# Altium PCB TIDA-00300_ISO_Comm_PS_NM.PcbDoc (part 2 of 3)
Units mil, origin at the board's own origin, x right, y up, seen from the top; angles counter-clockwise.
Board outline 2559.06 x 6299.21 mil, 4 copper layers (Top Layer, GND Layer, PWR Layer, Bottom Layer), stack 61.6 mil thick; 303 components, 144 nets, 678 pads, 244 vias.
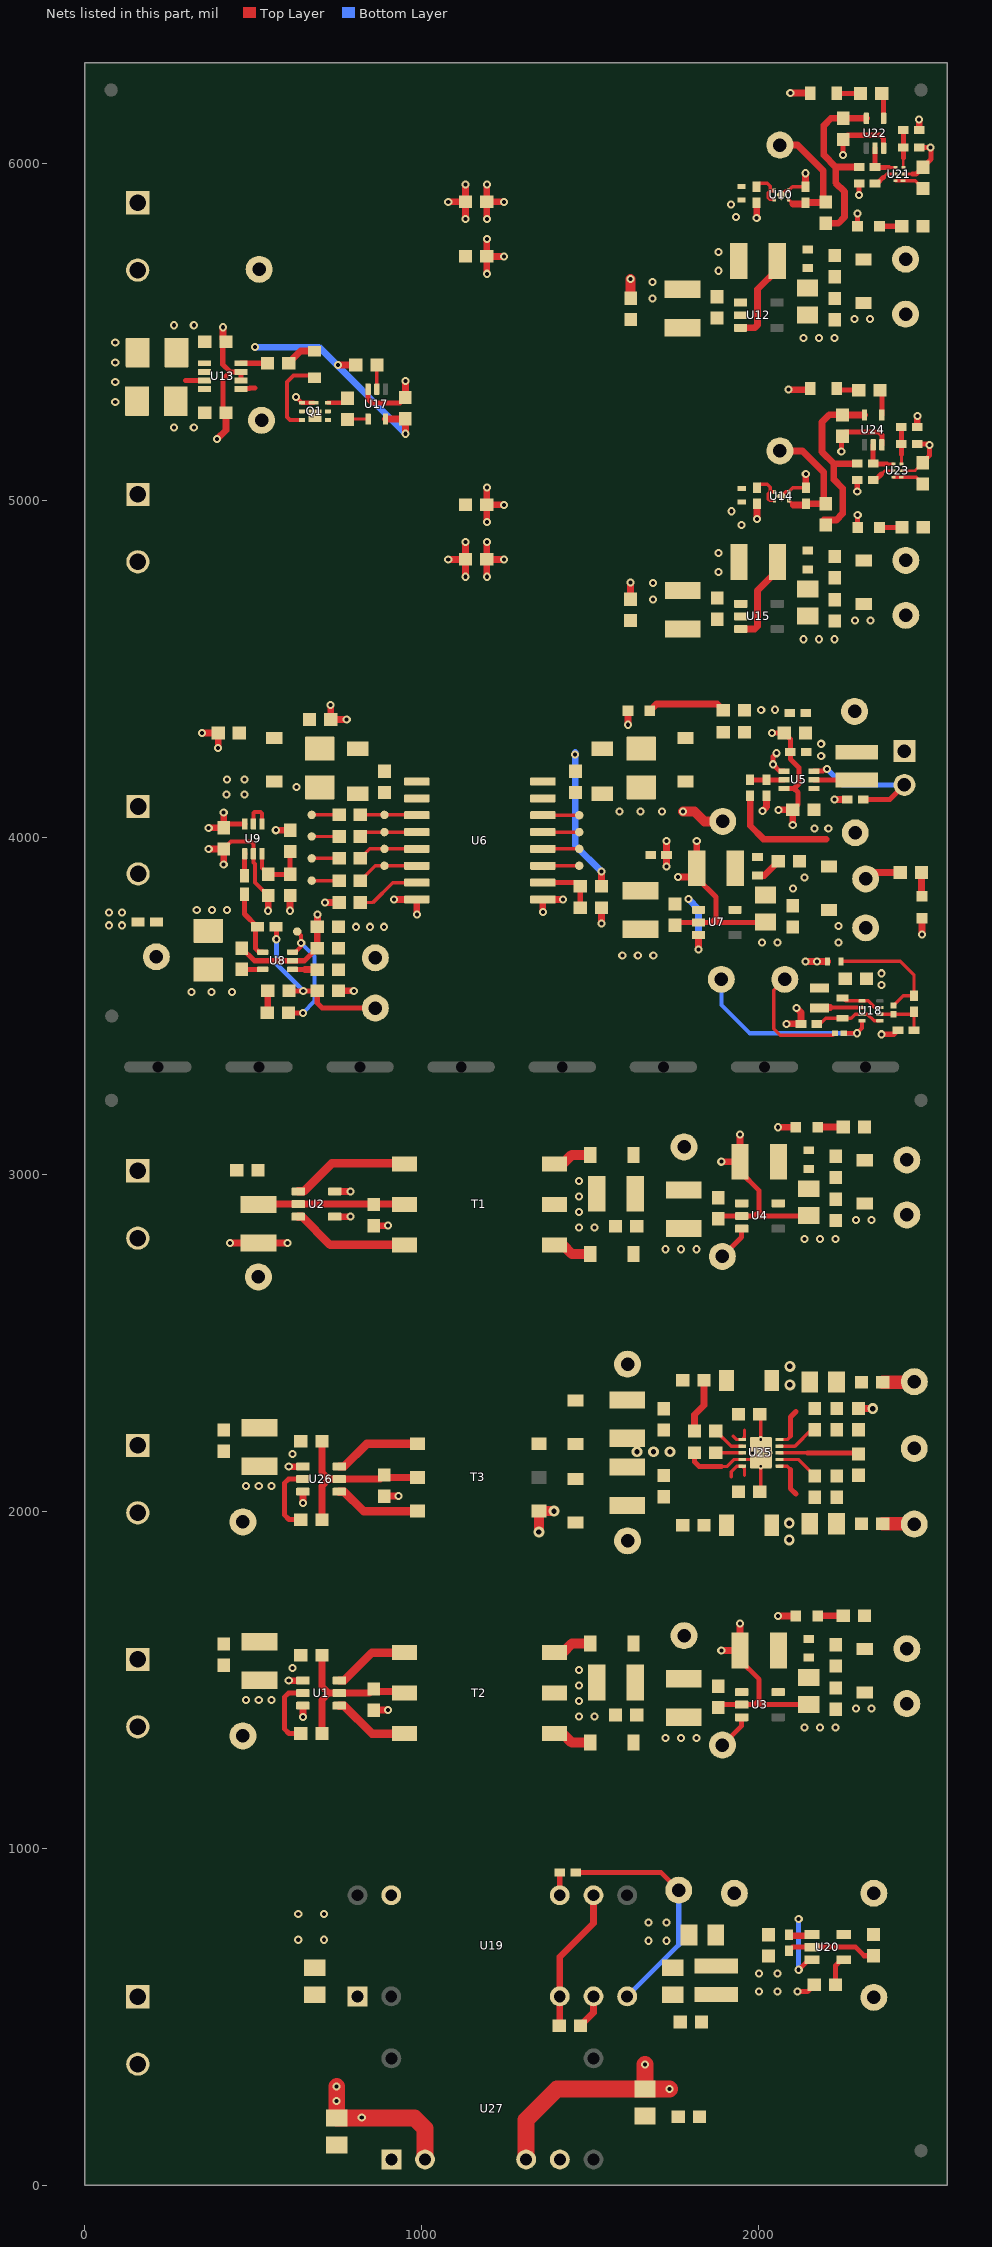
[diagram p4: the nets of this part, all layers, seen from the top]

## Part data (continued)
L8: library part CMP-0058850-1, "Inductor, Wirewound, Ferrite, 15 uH, 0.37 A, 0.91 ohm, SMD", Manufacturer=MuRata, Supplier Part Number 1=490-5124-1-ND, Value1="0.91 ohm", Value2=0.37A, ValueDisplayed=15uH
Logo2: library part Pb-Free
Logo3: library part FCC_disclaimer, "FCC_disclaimer"
Logo4: library part CMP-0074769-1
Logo5: library part ESD_Susceptible, "ESD Susceptible Symbol"
Q1: "MOSFET, N-CH, 30 V, 22 A, DQK0006C (WSON-6)", Alternate Manufacturer=None, Manufacturer="Texas Instruments", Supplier Part Number 1=296-37193-1-ND, Value1="0.029 ohm", Value2="2.4 nC"
R1 R2 R3 R4 R5 R23 R40 R47 R82 R85 R94 R95: "RES, 0 ohm, 5%, 0.1W, 0603", Manufacturer=Vishay-Dale, Power_W=0.1, Supplier Part Number 1=541-0.0GCT-ND, TempCo="200 ppm/C", Tolerance_%=5, Value1=5%, Value2=0.1W, Value_Code=0000
R6 R7 R11: "RES, 820, 1%, 0.1 W, 0603", Manufacturer="Yageo America", Power_W=0.1, Supplier Part Number 1=311-820HRCT-ND, TempCo="200 ppm/C", Tolerance_%=1, Value1=1%, Value2=0.1W, Value_Code=820R, ValueDisplayed=820
R8 R9 R10 R20 R22 R25 R35 R36 R37 R38 R61 R63 R72 R77 R83 R84 R89 R90 R92: "RES, 0, 5%, 0.1 W, 0603", Manufacturer=Vishay-Dale, Power_W=0.1, Supplier Part Number 1=541-0.0GCT-ND, TempCo="200 ppm/C", Tolerance_%=5, Value1=5%, Value2=0.1W, Value_Code=0000, ValueDisplayed=0
R12 R65 R70: "RES, 0, 5%, 0.063 W, 0402", Manufacturer=Vishay-Dale, Power_W=0.063, Supplier Part Number 1=541-0.0JCT-ND, TempCo="200 ppm/C", Tolerance_%=5, Value1=5%, Value2=0.063W, Value_Code=0000, ValueDisplayed=0
R13 R15: "RES, 1.00 M, 1%, 0.063 W, 0402", Manufacturer=Vishay-Dale, Power_W=0.063, Supplier Part Number 1=541-1.00MLCT-ND, TempCo="100 ppm/C", Tolerance_%=1, Value1=1%, Value2=0.063W, Value_Code=1M00, ValueDisplayed=1.00M
R14 R16 R18 R19: "RES, 49.9, 1%, 0.1 W, 0603", Manufacturer=Vishay-Dale, Power_W=0.1, Supplier Part Number 1=541-49.9HCT-ND, TempCo="100 ppm/C", Tolerance_%=1, Value1=1%, Value2=0.1W, Value_Code=49R9, ValueDisplayed=49.9
R17 R60: "RES, 100 k, 1%, 0.0625 W, 0402", Manufacturer="Yageo America", Power_W=0.0625, Supplier Part Number 1=311-100KLRCT-ND, TempCo="100 ppm/C", Tolerance_%=1, Value1=1%, Value2=0.0625W, Value_Code=100k
R21: "RES, 4.7 k, 5%, 0.1 W, 0603", Manufacturer="Yageo America", Power_W=0.1, Supplier Part Number 1=311-4.7KGRCT-ND, TempCo="100 ppm/C", Tolerance_%=5, Value1=5%, Value2=0.1W, Value_Code=4k70, ValueDisplayed=4.7k
R24 R41 R48 R54 R75 R80: "RES, 680, 1%, 0.1 W, 0603", Manufacturer="Yageo America", Power_W=0.1, Supplier Part Number 1=311-680HRCT-ND, TempCo="200 ppm/C", Tolerance_%=1, Value1=1%, Value2=0.1W, Value_Code=680R, ValueDisplayed=680
R26 R29 R71: "RES, 47 k, 5%, 0.1 W, 0603", Manufacturer="Yageo America", Power_W=0.1, Supplier Part Number 1=311-47KGRCT-ND, TempCo="100 ppm/C", Tolerance_%=5, Value1=5%, Value2=0.1W, Value_Code=47k0, ValueDisplayed=47k
R27: "RES, 2.20 k, 1%, 0.1 W, 0603", Manufacturer="Yageo America", Power_W=0.1, Supplier Part Number 1=311-2.20KHRCT-ND, TempCo="200 ppm/C", Tolerance_%=1, Value1=1%, Value2=0.1W, Value_Code=2k20, ValueDisplayed=2.20k
R28 R31 R32: "RES, 0 ohm, 5%, 0.063W, 0402", Manufacturer="Yageo America", Power_W=0.063, Supplier Part Number 1=311-0.0JRCT-ND, TempCo="200 ppm/C", Tolerance_%=5, Value1=5%, Value2=0.063W, Value_Code=0000
R30 R33: "RES, 162 k, 1%, 0.1 W, 0603", Manufacturer="Yageo America", Power_W=0.1, Supplier Part Number 1=311-162KHRCT-ND, TempCo="200 ppm/C", Tolerance_%=1, Value1=1%, Value2=0.1W, Value_Code=162k
R34 R44 R57: library part CMP-0027004-2, "RES, 0, 5%, 0.063 W, 0402", Manufacturer="Yageo America", Power_W=63mW, Supplier Part Number 1=311-0.0JRCT-ND, TempCo="200 ppm/C", Tolerance_%=5%, Value2=0.063W, Value_Code=0000, ValueDisplayed=0
R55: "RES, 300, 5%, 0.1 W, 0603", Manufacturer=Vishay-Dale, Power_W=0.1, Supplier Part Number 1=541-300GCT-ND, TempCo="200 ppm/C", Tolerance_%=5, Value1=5%, Value2=0.1W, Value_Code=300R, ValueDisplayed=300
R56: "RES, 0, 1%, 0.1 W, AEC-Q200 Grade 0, 0603", Manufacturer="Stackpole Electronics Inc", Power_W=0.1, Supplier Part Number 1=RMCF0603ZT0R00CT-ND, TempCo=ppm/C, Tolerance_%=1, Value1=1%, Value2=0.1W, Value_Code=0
R58: "RES, 453 k, 1%, 0.063 W, 0402", Manufacturer=Vishay-Dale, Power_W=0.063, Supplier Part Number 1=541-453KLCT-ND, TempCo="100 ppm/C", Tolerance_%=1, Value1=1%, Value2=0.063W, Value_Code=453k
R59: library part CMP-0027293-2, "RES, 100 k, 1%, 0.05 W, 0201", Manufacturer="Yageo America", Power_W=50mW, Supplier Part Number 1=311-100KMCT-ND, TempCo="200 ppm/C", Tolerance_%=1%, Value2=0.05W, Value_Code=100k
R73 R78: "RES, 68 k, 5%, 0.063 W, 0402", Manufacturer=Vishay-Dale, Power_W=0.063, Supplier Part Number 1=541-68KJCT-ND, TempCo="200 ppm/C", Tolerance_%=5, Value1=5%, Value2=0.063W, Value_Code=68k0, ValueDisplayed=68k
R74 R76 R79 R81 R93: "RES, 10.0 k, 1%, 0.063 W, 0402", Manufacturer=Vishay-Dale, Power_W=0.063, Supplier Part Number 1=541-10.0KLCT-ND, TempCo="100 ppm/C", Tolerance_%=1, Value1=1%, Value2=0.063W, Value_Code=10k0, ValueDisplayed=10.0k
R86 R87: "RES, 274 k, 1%, 0.1 W, 0603", Manufacturer=Vishay-Dale, Power_W=0.1, Supplier Part Number 1=541-274KHCT-ND, TempCo="100 ppm/C", Tolerance_%=1, Value1=1%, Value2=0.1W, Value_Code=274k
R88: "RES, 31.6 k, 1%, 0.1 W, 0603", Manufacturer=Vishay-Dale, Power_W=0.1, Supplier Part Number 1=541-31.6KHCT-ND, TempCo="100 ppm/C", Tolerance_%=1, Value1=1%, Value2=0.1W, Value_Code=31k6, ValueDisplayed=31.6k
R91: "RES, 27.4 k, 1%, 0.1 W, 0603", Manufacturer=Vishay-Dale, Power_W=0.1, Supplier Part Number 1=541-27.4KHCT-ND, TempCo="100 ppm/C", Tolerance_%=1, Value1=1%, Value2=0.1W, Value_Code=27k4, ValueDisplayed=27.4k
T1 T2: library part 750313734, "Transformer, 340 uH, TH", Manufacturer="Wurth Elektronik", Supplier Part Number 1=1297-1105-1-ND, ValueDisplayed=340µH
T3: library part CMP-0030718-1, "Transformer, 475uH, SMT", Manufacturer="Wurth Elektronik", Supplier Part Number 1=732-4458-1-ND, ValueDisplayed=475uH
TP1 TP2 TP7 TP8 TP11 TP12 TP19 TP27 TP28 TP29 TP30 TP33 TP36 TP38 TP39 TP41 TP51 TP53 TP54 TP55 TP56 TP59 TP60 TP61: "Test Point, Miniature, Red, TH", Color=Red, Manufacturer=Keystone, Supplier Part Number 1=36-5000-ND
TP3 TP4 TP5 TP6 TP23 TP26 TP35 TP43 TP52 TP57 TP58: "Test Point, Miniature, Black, TH", Color=Black, Manufacturer=Keystone, Supplier Part Number 1=36-5001-ND
TP9 TP10 TP31: "Test Point, Miniature, White, TH", Color=White, Manufacturer=Keystone, Supplier Part Number 1=36-5002-ND
TP13 TP14 TP15 TP16 TP17 TP18 TP20 TP21 TP22 TP45 TP46 TP47 TP48: "Test Point, O.025\"", Manufacturer=STD
U1 U26: "LOW-NOISE 1A TRANSFORMER DRIVERS FOR ISOLATED POWER SUPPLIES, DBV0006A", Alternate Manufacturer="Texas Instruments", Alternate PartNumber=SN6505BDBVT
U2: "Transformer Driver for Isolated Power Supplies, DBV0005A", Alternate Manufacturer="Texas Instruments", Alternate PartNumber=SN6501DBVT, Supplier Part Number 1=296-37700-1-ND
U3: library part CMP-0073793-1, "150-mA, 30-V, Ultra-Low IQ, Wide Input Low-Dropout Regulator with Reverse Current Protection, DBV0005A (SOT-23-5)", Alternate Manufacturer="Texas Instruments", Alternate PartNumber=TPS70933DBVT
U4: library part CMP-0066783-1, "150-mA, 30-V, Ultra-Low IQ, Wide Input Low-Dropout Regulator with Reverse Current Protection, DBV0005A (SOT-23-5)", Alternate Manufacturer="Texas Instruments", Alternate PartNumber=TPS70950DBVT
U5: library part CMP-0067204-1, "Low Input Voltage, 0.7V Boost Converter with 5.5uA Quiescent Current, DCK0006A (SOT-SC70-6)", Alternate Manufacturer="Texas Instruments", Alternate PartNumber=TPS61220DCKT
U6: library part ISOW7841DWR, "ISOW7841DWE, DW0016B (SOIC-16)", Alternate Manufacturer="Texas Instruments", Alternate PartNumber=ISOW7841DW, Supplier Partnumber 1=296-45475-1-ND
U7: library part CMP-0035560-1, "Single Output LDO, 150 mA, Fixed 5 V Output, 2.7 to 10 V Input, with Low IQ, 5-pin SOT-23 (DBV), -40 to 125 degC, Green (RoHS & no Sb/Br)", Manufacturer="Texas Instruments"
U8: "LOW-INPUT-VOLTAGE CURRENT-LIMITED LOAD SWITCHES WITH SHUT OFF AND AUTO-RESTART FEATURE, DCK0005A (SOT-5)", Alternate Manufacturer="Texas Instruments", Supplier Part Number 1=296-25218-1-ND
U9: "Nanopower, 1.8V, Comparator with Voltage Reference, DCK0006A", Alternate Manufacturer="Texas Instruments", Alternate PartNumber=TLV3012AIDCKT, Supplier Part Number 1=296-26816-1-ND
U10 U14: library part CMP-0079101-1, "200-mA, Small Size, Low-Dropout Linear Voltage Regulator, DQN0004A (X2SON-4)", Alternate Manufacturer="Texas Instruments"
U12 U15: "Single Output LDO, 150 mA, Fixed 5 V Output, 2.5 to 24 V Input, with Ultra-Low IQ, 5-pin SOT-23 (DBV), -40 to 125 degC, Green (RoHS & no Sb/Br)", Alternate Manufacturer="Texas Instruments", Alternate PartNumber=Equivalent, Supplier Part Number 1=296-39287-1-ND
U13: library part CMP-0066654-1, "5.5V, 0.5A, 435mO, 2-Channel Load Switch with Quick Output Discharge, DCN0008A (SOT-23-8)", Alternate Manufacturer="Texas Instruments"
U17: library part CMP-0051641-4, "Single Schmitt-Trigger Inverter, DCK0005A (SOT-SC70-5)", Alternate Manufacturer="Texas Instruments", Alternate PartNumber=SN74LVC1G14DCKT, F @ Nom Voltage(Max)(Mhz)=150, Generic Part Number=SN74LVC1G14, ICC @ Nom Voltage(Max)(mA)=0.01, Operating Temperature Range="-40 to 125 C", Rating=Catalog, tpd @ Nom Voltage(Max)(ns)=11,6.5,5.5,5, Voltage(Nom)(V)=1.8,2.5,3.3,5
U18: library part CMP-0065148-3, "1A Step-Down Converter With 1% Accuracy, DLC0008A (VSON-HR-8)", Alternate Manufacturer="Texas Instruments"
U19: library part CMP-0030829-1, "Miniature, 1 W Isolated Regulated DC-DC Converter, -40 to 85 degC, 10-pin DIP (NVE10), Pb-Free (RoHS)", Manufacturer="Texas Instruments"
U20: "Micropower 150 mA Low-Noise Ultra Low-Dropout Regulator, 5-pin SOT-23, Pb-Free", Manufacturer="Texas Instruments", PackageTopMarking=L0RA*XTT, PowerWise=N, Supplier Part Number 1=LP2985AIM5-3.3CT-ND
U21: library part CMP-0032427-1, "Single Channel, Ultra Small, Adjustable Supervisory Circuit with Active-High, Open-Drain Output, 1 Supply Monitored, -40 to 125 degC, 6-pin SON (DRY), Green (RoHS & no Sb/Br)", Manufacturer="Texas Instruments", Rating=Catalog, Threshold Voltage 1 (typ)(Typ)(V)=Adjustable
U22 U24: library part CMP-0051704-1, "Single Schmitt-Trigger Buffer, DCK0005A, LARGE T&R", F @ Nom Voltage(Max)(Mhz)=150, Generic Part Number=SN74LVC1G17, ICC @ Nom Voltage(Max)(mA)=0.01, Manufacturer="Texas Instruments", Operating Temperature Range(C)="-40 to 125,-40 to 85", Rating=Catalog, tpd @ Nom Voltage(Max)(ns)=11,6.5,5.5,5, Voltage(Nom)(V)=1.8,2.5,3.3,5
U23: library part CMP-0032419-1, "Single Channel, Ultra Small, Adjustable Supervisory Circuit with Active-High, Push-Pull Output, 1 Supply Monitored, -40 to 125 degC, 6-pin SON (DRY), Green (RoHS & no Sb/Br)", Manufacturer="Texas Instruments", Rating=Catalog, Threshold Voltage 1 (typ)(Typ)(V)=Adjustable
U25: "Wide-VIN (±33 V), 150-mA, Spilt-Rail Output, Positive and Negative LDO Voltage Regulator with Startup Tracking, DSC0010J", Alternate Manufacturer="Texas Instruments", Supplier Part Number 1=296-47504-1-ND
U27: library part CMP-0030762-1, "Miniature, 1 W Isolated Unregulated DC-DC Converter, -40 to 100 degC, 7-pin DIP (NVA7), Pb-Free (RoHS)", Manufacturer="Texas Instruments"
ZZ1: library part AssemblyNoteLabel
ZZ2 ZZ3 ZZ4: library part AssemblyNote

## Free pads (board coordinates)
  oval 200x32 hole 32 slot 200 at 0 deg unplated mask+10: 0(216.42,3318.94) 0(516.42,3318.94) 0(816.42,3318.94) 0(1116.42,3318.94) 0(1416.42,3318.94) 0(1716.42,3318.94) 0(2016.42,3318.94) 0(2316.42,3318.94)

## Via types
v1: diameter 24, hole 12, Top Layer to Bottom Layer, 230 vias
v2: diameter 32, hole 16, Top Layer to Bottom Layer, 10 vias
v3: diameter 19.68, hole 7.87, Top Layer to Bottom Layer, 4 vias

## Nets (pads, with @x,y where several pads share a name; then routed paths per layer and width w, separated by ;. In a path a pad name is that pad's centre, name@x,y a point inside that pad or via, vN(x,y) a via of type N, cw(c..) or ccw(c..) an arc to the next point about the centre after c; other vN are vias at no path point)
+3.3V_6: C79.1 TP53.1 U20.5
+3.3V_VDC_1: D5.1 R4.2 R7.2 TP7.1
+5.0V_3.3V_VDC_4: C82.1 C83.1 D16.1 R40.2 R41.2 R72.1 R74.1 TP33.1 U21.1 U21.6 U22.5 | length 657.4
  Top Layer w10: U21.6@2405.03,5948.79 U21.1@2427.67,5948.79 2427.67,5948.11 2464.42,5948.11 C82.1@2486.84,5925.69
  Top Layer w20: R72.1@2198,5822.35 2235.5,5822.35 2254,5840.85 2254,5916.13 2227.79,5942.34 2227.79,5989.06 ; R74.1@2297.22,5989.06 2227.79,5989.06 ; U22.5@2318.87,6133.77 2250.05,6133.77 C83.1@2249.84,6133.98 2213.89,6133.98 2192.47,6112.56 2192.47,6024.38 2227.79,5989.06
+5.0V_3.3V_VDC_5: C85.1 C86.1 D20.1 R47.2 R48.2 R77.1 R79.1 TP41.1 U23.1 U23.6 U24.5 | length 661.7
  Top Layer w10: U23.6@2399.56,5068.66 U23.1@2422.19,5068.66 ; U23.1@2422.19,5067.97 U23.1@2422.19,5068.66 ; C85.1@2486.57,5048.53 2466.43,5068.66 U23.1@2422.19,5068.66
  Top Layer w20: R77.1@2192.53,4942.22 2230.03,4942.22 2248.53,4960.72 2248.53,5035.99 2222.31,5062.21 2222.31,5108.93 ; R79.1@2291.75,5108.93 2222.31,5108.93 ; U24.5@2313.4,5253.64 2244.57,5253.64 2244.37,5253.84 2208.42,5253.84 2187,5232.42 2187,5144.24 2222.31,5108.93
+5.0V_VDC_2: D6.1 R5.2 R6.2 TP8.1
+5.0V_VDC_3: C33.2 C34.1 D12.1 R23.2 R24.2 R57.2 TP28.1 | length 176
  Top Layer w20: v1(2138.26,3631.85) v1(2172.77,3631.85) R57.2@2203.82,3631.85 ; TP28.1@2316.77,3876.85 2335.88,3895.96 R24.2@2419.27,3895.96
  other v1: 2100.84,3847.85 2135.14,3881.53
+5V_1: J1.1 R1.2
+5V_2: J2.1 R2.2
+5V_B: J8.1 R82.2
+5V_VDC_6: C75.1 C77.1 C78.1 L8.2 TP51.1 U20.1 U20.3 | length 272.9
  Top Layer w15: v1(2118,640) 2147.6,669.6 U20.3@2157.39,669.6
  Top Layer w20: C78.1@2088.64,743.62 2091.26,741 2153.99,741 U20.1@2157.39,744.4
  Bottom Layer w15: v1(2118,640) v1(2118,790)
+6V_VDC_1: C8.1 C9.1 C10.2 C12.1 D2.1 D4.1 TP2.1 U3.1
+6V_VDC_2: C6.1 C7.1 C11.2 C13.1 D1.1 D3.1 TP1.1 U4.1
+12V: R83.2 TP56.1 | length 94.4
  Top Layer w40: R83.2@2367.07,2383.67 2459.82,2383.67 TP56.1@2461,2384.85
-12V: R92.2 TP60.1 | length 94.3
  Top Layer w40: R92.2@2367.07,1963.67 2459.58,1963.67 TP60.1@2460.86,1962.39
C\S\: R18.2 TP47.1 | length 81.5
  Top Layer w10: TP47.1@672.77,3937.85 R18.2@754.27,3937.85
DVDD_3: C29.1 C30.2 C37.1 R8.2 R20.2 R26.2 R30.2 R32.2 R71.2 TP27.1 U8.5 U9.6 | length 461.1
  Top Layer w15: C37.1@411.77,4028.35 423.56,4040.14 U9.6@474.18,4040.14 ; C30.2@465.57,3608.5 465.66,3608.4 U8.5@527.48,3608.4
  Top Layer w20: v1(347.77,4309.85) R8.2@395.27,4309.85 395.27,4265.35 v1(394.77,4264.84) ; v1(367.27,4028.35) C37.1@411.77,4028.35 ; C37.1@411.77,4028.85 v1(411.77,4073.35) ; R71.2@541.27,3479.14 542.27,3480.14 R26.2@542.27,3544.85 ; v1(566.27,4021.35) R30.2@608.77,4021.35 ; v1(712.77,3806.85) R20.2@754.27,3806.85
  other v1: 315.77,3541.85 375.77,3541.85 435.77,3541.85
DVDD_4: C52.1 C53.2 J5.2 U13.1 U13.2
  other v1: 264,5519.8 323,5519.8
DVDD_5: C54.1 C55.2 J6.1 U13.3 U13.4 | length 55.9
  Top Layer w15: 299,5355.8 U13.3@354.87,5355.8
  other v1: 264,5215.8 323,5215.8
DVDD_I_3: R9.2 R11.2 R12.1 R65.2 TP11.1 | length 95.4
  Top Layer w20: v1(2081.77,3446.85) 2124.28,3446.85 R65.2@2124.67,3446.46 2124.67,3480.53 v1(2111.77,3493.43)
  other v1: 2006.77,4377.85 2047.72,4378.85
DVDD_I_4: R34.1 R35.1 R61.2 R73.2 | length 242.9
  Top Layer w20: v1(1192.5,5672.5) R35.1@1192.5,5724 ; v1(1192.5,5775.5) R35.1@1192.5,5724 ; v1(1243.99,5724) R35.1@1192.5,5724 ; R73.2@2475.46,6098.48 v1(2475.46,6130.39)
  Top Layer w30: R61.2@1619.42,5599.99 v1(1619.42,5656.44)
  other v1: 1932.42,5841.49 1917.42,5878.52
DVDD_I_5: R37.1 R44.1 R63.2 R78.2 | length 236.6
  Top Layer w20: v1(1192.5,4935.5) R37.1@1192.5,4987 ; v1(1192.5,5038.5) R37.1@1192.5,4987 ; v1(1243.99,4987) R37.1@1192.5,4987 ; v1@1618.74,4756.8 v1(1619,4756.55) R63.2@1619,4706.66 ; R78.2@2469.99,5218.35 v1(2469.99,5250.25)
  other v1: 1948.07,4926.8 1919,4967.8
DVDD_I_5.4V_3: C28.1 R13.2 R70.1 TP12.1 U5.4 | length 408
  Top Layer w20: v1(1725.72,3913.32) R70.1@1725.72,3947.85 v1(1725.72,3989.84) ; R13.2@1974.11,4123.99 1974.11,4034.57 2013.84,3994.85 2199.77,3994.85
  other v1: 2164.77,4026.85 2205.77,4026.85
GND_1: C2.1 C3.1 C5.1 J1.2 TP3.1 U1.4 U1.6 | length 117.5
  Top Layer w15: U1.6@646.61,1423.45 U1.6@646.74,1423.31
  Top Layer w20: v1(604.74,1497.85) 646.21,1497.85 U1.4@646.48,1498.12 ; v1(646.74,1389.85) U1.6@646.74,1423.31 ; C5.1@856.88,1410.49 857.24,1410.85 v1(898.74,1410.85)
  other v1: 477.74,1440.85 515.74,1440.85 553.74,1440.85 615.74,1534.85
GND_2: C1.1 C4.1 J2.2 TP4.1 U2.4 U2.5 | length 305.9
  Top Layer w20: v1(430.83,2796.72) C1.1@514.74,2796.72 v1(601.66,2796.72) ; U2.4@741.36,2874.64 v1(787.91,2874.64) ; U2.5@741.36,2949.44 v1(787.91,2949.44) ; C4.1@856.88,2847.58 857.24,2847.94 v1(898.74,2847.94)
GND_3: C20.1 C22.2 C24.2 C29.2 C30.1 C36.1 C37.2 C38.2 D9.2 J4.1 R27.2 R29.1 R33.1 U6.2 U6.8 U8.2 U9.2 | length 965.4
  Top Layer w12: C37.2@411.77,3965.35 433.81,3987.39 493.49,3987.39 499.77,3981.12 U9.2@499.77,3951.56 499.77,3925.59 504.77,3920.59 504.77,3866.35 R33.1@543.77,3827.35
  Top Layer w15: C30.1@465.57,3671.49 503.06,3633.99 U8.2@616.06,3633.99 651.77,3633.99 C36.1@689.27,3671.49
  Top Layer w20: v1(367.27,3965.35) C37.2@411.77,3965.35 v1(411.77,3919.95) ; v1(543.77,3782.35) R33.1@543.77,3827.35 ; v1(608.7,3782.35) C38.2@608.7,3827.35 ; C36.1@689.27,3671.49 R27.2@689.27,3734.85 689.77,3735.35 v1(689.77,3771.85) ; R29.1@752.26,3544.85 v1(797.77,3544.85) ; v1(916.77,3815.85) U6.8@984.76,3815.85 v1(984.76,3770.86)
  other v1: 331.77,3785.17 376.77,3784.85 421.77,3784.54 419.77,4126.85 473.45,4126.85 627.77,4149.17 421.08,4171.85 473.77,4171.85
GND_4: C52.2 C53.1 C54.2 C55.1 C69.2 J5.1 J6.2 Q1.4 Q1.7 R36.2 R38.2 U13.6 U13.7 U17.3 | length 999.1
  Top Layer w12: v1(626.57,5307.46) Q1.4@644.23,5289.8 Q1.7@678.87,5289.8
  Top Layer w15: C55.1@418.5,5260.6 410,5269.09 410,5360.4 430.99,5381.39 ; C53.1@418.5,5470.6 409,5461.1 409,5403.39 430.99,5381.39 ; U13.6@463.13,5355.8 U13.7@463.13,5381.39 430.99,5381.39 ; U17.3@840.41,5330.09 840.41,5299.39 851,5288.8 934.5,5288.8 C69.2@951,5305.3
  Top Layer w20: v1(392,5181.8) 418.5,5208.3 C55.1@418.5,5260.6 ; v1(410,5513.8) 410,5479.09 C53.1@418.5,5470.6 ; C69.2@951,5305.3 v1(951,5353.8) ; v1(1078.01,4825) R38.2@1129.5,4825 ; v1(1078.01,5886) R36.2@1129.5,5886 ; v1(1129.5,4773.5) R38.2@1129.5,4825 ; v1(1129.5,4876.5) R38.2@1129.5,4825 ; v1(1129.5,5834.5) R36.2@1129.5,5886 ; v1(1129.5,5937.5) R36.2@1129.5,5886
  other v1: 90,5291.8 90,5350.8 90,5409.8 90,5468.8
GND_6: C73.2 C103.2 J7.1 U19.17 U27.2 | length 460.9
  Top Layer w50: v1(747,294) C103.2@747,200 978,200 1009.17,168.83 U27.2@1009.17,77
  other v1: 821.37,202 746,250 633,729 709,729 633,805 709,805
GND_B: C87.1 C88.1 C89.1 J8.2 TP57.1 U26.4 U26.6 | length 117.5
  Top Layer w15: U26.6@646.61,2058.45 U26.6@646.74,2058.31
  Top Layer w20: v1(604.74,2132.85) 646.21,2132.85 U26.4@646.48,2133.12 ; v1(646.74,2024.85) U26.6@646.74,2058.31 ; C89.1@888.77,2045.49 889.13,2045.85 v1(930.64,2045.85)
  other v1: 477.74,2075.85 515.74,2075.85 553.74,2075.85 615.74,2169.85
GND_BI: C90.1 C91.2 C93.2 C94.2 C95.2 C97.2 C98.2 C99.1 C100.1 C101.1 C102.2 R88.1 T3.4 TP58.1 U25.4 U25.11@2005.58,2173.87 | length 627.4
  Top Layer w10: 1888.86,2133.39 1905.86,2133.39 1926.65,2154.18 U25.4@1950.46,2154.18 1985.89,2154.18 U25.11@2005.58,2173.87 ; C102.2@2002.07,2058.67 2005.58,2062.17 v3(2005.58,2134.5) U25.11@2005.58,2173.87 ; C91.2@2002.07,2288.67 2005.58,2285.17 v3(2005.58,2213.24) U25.11@2005.58,2173.87
  Top Layer w15: C98.2@1809.08,2173.67 1809.08,2147.17 1822.86,2133.39 1888.86,2133.39
  Top Layer w20: R88.1@2295.58,2305.17 v2(2337.63,2305.17)
  Top Layer w30: v2(1347,1938.85) T3.4@1347,2000.85 v2(1392,2000.85)
  other v2: 2089.86,1915.39 2089.86,1965.39 1638,2176.85 1687,2176.85 1736,2176.85 2091.86,2375.39 2091.86,2430.39
  other v3: 1980.97,2173.87 2030.19,2173.87
GND_VDC_1: C8.2 C9.2 C10.1 C12.2 C14.1 C16.2 C18.1 D5.2 D7.1 T2.5 TP6.1 U3.2 | length 685.6
  Top Layer w15: C12.2@1879.02,1418.07 1887.52,1426.56 U3.2@1948.89,1426.56 2000.74,1426.56 ; C18.1@1943.93,1587.56 1943.93,1558.66 2000.74,1501.85 2000.74,1426.56 ; 1986.74,1426.56 2000.74,1440.56 2014.74,1426.56 ; C14.1@2148.02,1427.56 2147.02,1426.56 2000.74,1426.56
  Top Layer w20: v1(1888.28,1587.56) C18.1@1943.93,1587.56 1943.93,1667.66 v1(1943.74,1667.85) ; v1(2056.74,1689.85) 2109.18,1689.85 D7.1@2109.26,1689.76
  other v1: 1722.74,1327.85 1768.74,1327.85 1814.74,1327.85 2135.74,1358.85 2181.74,1358.85 2227.74,1358.85 1465.74,1391.85 1511.74,1391.85 2287.74,1414.99 2333.74,1414.99 1465.74,1437.85 1465.74,1483.85 1465.74,1529.85
GND_VDC_2: C6.2 C7.2 C11.1 C13.2 C15.1 C17.2 C19.1 D6.2 D8.1 T1.5 TP5.1 U4.2 | length 685.6
  Top Layer w15: C13.2@1879.02,2868.16 1887.52,2876.66 U4.2@1948.89,2876.66 2000.74,2876.66 ; C19.1@1943.93,3037.66 1943.93,3008.76 2000.74,2951.94 2000.74,2876.66 ; 1986.74,2876.66 2000.74,2890.66 2014.74,2876.66 ; C15.1@2148.02,2877.66 2147.02,2876.66 2000.74,2876.66
  Top Layer w20: v1(1888.28,3037.66) C19.1@1943.93,3037.66 1943.93,3117.76 v1(1943.74,3117.94) ; v1(2056.74,3139.94) 2109.18,3139.94 D8.1@2109.26,3139.86
  other v1: 1722.74,2777.94 1768.74,2777.94 1814.74,2777.94 2135.74,2808.94 2181.74,2808.94 2227.74,2808.94 1465.74,2841.94 1511.74,2841.94 2287.74,2865.08 2333.74,2865.08 1465.74,2887.94 1465.74,2933.94 1465.74,2979.94
GND_VDC_6: C74.2 C75.2 C76.2 C77.2 C78.2 C79.2 C80.2 C104.2 TP52.1 U19.8 U20.2 U27.5 | length 1081.3
  Top Layer w15: C78.2@2088.64,696.38 2099.26,707 U20.2@2157.39,707 2287,707 2312.5,681.5 C79.2@2340,681.5 ; v1(2114.74,575) 2144.5,575 C80.2@2164.5,595
  Top Layer w20: C76.2@1470.5,474 1509,512.5 U19.8@1509,561
  Top Layer w50: U27.5@1309.17,77 1309.17,194.17 1400.91,285.91 C104.2@1661.72,285.91 ; v1(1661.72,359) C104.2@1661.72,285.91 ; v1(1734.91,285.91) C104.2@1661.72,285.91
  other v1: 2000.74,575 2054.74,575 2000.74,629 2054.74,629 1672,726 1726,726 1672,780 1726,780
I_C\S\: TP20.1 U6.12 | length 108
  Top Layer w10: U6.12@1358.77,3965.85 TP20.1@1466.77,3965.85
I_SCLK: TP14.1 U6.14 | length 108
  Top Layer w10: U6.14@1358.77,4065.85 TP14.1@1466.77,4065.85
I_SDI: TP16.1 U6.13 | length 108
  Top Layer w10: U6.13@1358.77,4015.85 TP16.1@1466.77,4015.85
I_SDO: TP22.1 U6.11 | length 108
  Top Layer w10: U6.11@1358.77,3915.85 TP22.1@1466.77,3915.85
IGND_3: C21.1 C23.2 C25.2 C26.2 C27.1 C28.2 C31.1 C32.2 C33.1 C34.2 C35.1 C71.2 C72.2 D10.2 D11.1 D12.2 D13.1 R15.1 R17.1 R22.1 R60.1 TP23.1 TP26.1 U5.3 U6.9 U6.15 U7.2 U18.3 U18.5 | length 1706.8
  Top Layer w10: C71.2@2248.34,3523.38 2256.81,3514.91 U18.5@2305.77,3514.91 2324.71,3514.91 2344.4,3495.22 U18.3@2358.92,3495.22
  Top Layer w15: C32.2@1750.77,3739.27 1759.26,3747.76 U7.2@1820.63,3747.76 1872.49,3747.76 ; C35.1@1815.68,3908.76 1815.68,3879.86 1872.49,3823.05 1872.49,3747.76 ; 1858.49,3747.76 1872.49,3761.76 1886.49,3747.76 ; C33.1@2019.77,3748.76 2018.77,3747.76 1872.49,3747.76 ; v1(2038.77,4309.85) C26.2@2075.27,4309.85 2093.14,4291.98 C25.2@2093.14,4253.85 2093.14,4232.47 2118.77,4206.85 2118.77,4159.85 2104.18,4145.26 ; U5.3@2074.48,4145.26 2104.18,4145.26 ; C28.2@2100.27,4081.85 2115.77,4097.35 2115.77,4133.67 2104.18,4145.26 ; v1(2363.77,3415.85) 2400.77,3415.85 R60.1@2412.77,3427.85
  Top Layer w20: v1(1358.77,3778.86) U6.9@1358.77,3815.85 v1(1418.77,3815.85) ; v1(1532.77,3744.35) R22.1@1532.77,3791.85 ; v1(1611.29,4334.33) D11.1@1611.29,4375.85 ; v1(1759.77,3882.85) 1815.68,3882.85 C35.1@1815.68,3908.76 1815.68,3988.86 v1(1815.49,3989.05) ; v1(2010.07,4078.13) 2022.77,4090.83 R17.1@2022.77,4123.99 ; v1(2057.77,4081.85) C28.2@2100.27,4081.85 v1(2100.27,4036.35) ; v1(2223.77,4112.85) R15.1@2262.14,4112.85 ; v1(2483.77,3711.85) D13.1@2483.77,3760.28
  Top Layer w30: v1(1774.77,4076.85) 1808.84,4076.85 1838.16,4047.53 TP26.1@1892.56,4047.53
  other v1: 2363.77,3561.85 2363.84,3596.85 1594.49,3649.05 1640.49,3649.05 1686.49,3649.05 2008.77,3687.85 2054.77,3687.85 2235.77,3687.85 2235.77,3736.85 1585.77,4076.85 1648.77,4076.85 1711.77,4076.85
IGND_4: C39.2 C40.2 C47.1 C48.2 C49.1 C50.2 C51.1 C81.2 C82.2 C83.2 D16.2 D17.1 D23.1 R36.1 R76.1 TP35.1 U10.2 U10.5 U12.1 U21.2 U22.3 | length 826
  Top Layer w8: U21.2@2428.65,5968.48 2456,5968.48
  Top Layer w10: U10.5@2066.42,5906.29 2079.21,5919.08 U10.2@2087.48,5919.08 2099.49,5931.1 C40.2@2138.42,5931.1
  Top Layer w15: v1(2249.84,6024.85) C83.2@2249.84,6070.98 2262.43,6083.57 2360.28,6083.57 2370.05,6073.8 U22.3@2370.05,6045.19 ; D17.1@2292.42,5813.54 v1(2292.42,5850.78) ; v1(2297.22,5906.63) C81.2@2297.22,5940.06 ; 2456,5968.48 2466.64,5968.48 C82.2@2486.84,5988.68 2511,6012.84 2511,6045.11 v1(2508.63,6047.48) R76.1@2475.46,6047.48
  Top Layer w20: v1(1192.5,5834.5) R36.1@1192.5,5886 ; v1(1192.5,5937.5) R36.1@1192.5,5886 ; v1(1243.99,5886) R36.1@1192.5,5886 ; v1(1993.42,5838.49) C39.2@1993.42,5883.85 ; v1(2093,6208.85) 2152,6208.85 D23.1@2152.37,6208.48 ; v1(2138,5970.85) 2138,5931.51 C40.2@2138.42,5931.1
  other v1: 2132.14,5481.78 2178.14,5481.78 2224.14,5481.78 2284.14,5537.92 2330.14,5537.92 1684.42,5599.49 1684.42,5648.49 1879.42,5681.49 1879.42,5737.49
IGND_5: C56.2 C57.2 C64.1 C65.2 C66.1 C67.2 C68.1 C84.2 C85.2 C86.2 D20.2 D21.1 D24.1 R38.1 R81.1 TP43.1 U14.2 U14.5 U15.1 U23.2 U24.3 | length 828.2
  Top Layer w8: U23.2@2423.18,5088.35 2463.39,5088.35 C85.2@2486.57,5111.52
  Top Layer w10: U14.5@2067.07,5012.6 2079.87,5025.39 U14.2@2088.13,5025.39 2100.15,5037.41 C57.2@2139.07,5037.41
  Top Layer w15: v1(2244.37,5144.72) 2244.37,5190.85 2256.96,5203.44 2354.8,5203.44 2364.58,5193.66 U24.3@2364.58,5165.06 ; v1(2291.75,5026.5) C84.2@2291.75,5059.93 ; D21.1@2293.08,4919.85 v1(2293.08,4957.09) ; R81.1@2469.99,5167.35 2503.16,5167.35 v1(2505.53,5164.98) 2505.53,5132.71 C85.2@2485.45,5112.63
  Top Layer w20: v1(1192.5,4773.5) R38.1@1192.5,4825 ; v1(1192.5,4876.5) R38.1@1192.5,4825 ; v1(1243.99,4825) R38.1@1192.5,4825 ; v1(1994.07,4944.8) C56.2@1994.07,4990.16 ; v1(2087.53,5328.72) 2146.53,5328.72 D24.1@2146.9,5328.35 ; v1(2139,5078.85) 2139,5037.48 C57.2@2139.07,5037.41
  other v1: 2132.79,4588.09 2178.79,4588.09 2224.79,4588.09 2284.79,4644.23 2330.79,4644.23 1685.07,4705.8 1685.07,4754.8 1880.07,4787.8 1880.07,4843.8
ISO_VOUT: C21.2 C23.1 C27.2 D10.1 R9.1 R21.1 U6.16 | length 429.3
  Top Layer w20: R21.1@1532.77,3854.85 v1(1532.77,3898.85)
  Bottom Layer w20: v1@1454.77,4251.85 v1(1454.77,4245.85) 1454.77,3976.85 v1(1532.77,3898.85)
LS_CTRL: R28.1 R31.2 U8.4 | length 205
  Top Layer w15: R31.2@473.77,3831.29 473.77,3772.8 R28.1@511.71,3734.85 505.77,3728.91 505.77,3670.85 517.03,3659.58 U8.4@527.48,3659.58
NetC1_2: C1.2 C4.2 R2.1 T1.2 U2.2 | length 437.5
  Top Layer w20: C1.2@514.74,2910.89 515.89,2912.04 U2.2@633.09,2912.04 939.2,2912.04 943.11,2915.94 T1.2@948.11,2910.94
NetC2_2: C2.2 C3.2 C5.2 R1.1 R3.1 T2.2 U1.2 | length 483.8
  Top Layer w20: R3.1@703.24,1340.85 703.24,1440.65 723.44,1460.85 ; C3.2@703.24,1572.85 703.24,1481.05 723.44,1460.85 ; T2.2@948.11,1460.85 943.11,1465.85 864.24,1465.85 C5.2@856.74,1473.35 844.25,1460.85 U1.2@754.88,1460.85 723.44,1460.85
NetC14_2: C14.2 C16.1 L1.2 R4.1
NetC15_2: C15.2 C17.1 L2.2 R5.1
NetC18_2: C18.2 L1.1 U3.5
NetC19_2: C19.2 L2.1 U4.5
NetC20_2: C20.2 C22.1 C24.1 D9.1 R8.1 R10.1 U6.1
NetC25_1: C25.1 C26.1 J3.1 L3.1 R12.2 U5.1 | length 78.7
  Top Layer w15: v1(2051.72,4249.85) 2041.42,4239.55 v1(2041.42,4217.01) 2061.99,4196.44 U5.1@2074.48,4196.44
  other v1: 2184.77,4241.85 2184.77,4277.85
NetC31_2: C31.2 C32.1 R70.2 U7.1 U7.3 | length 203.7
  Top Layer w20: v1(1820.63,3667.98) U7.3@1820.63,3710.36
  Bottom Layer w20: v1(1790.44,3816.85) 1820.63,3786.66 v1(1820.63,3667.98)
NetC35_2: C35.2 L4.1 U7.5
NetC38_1: C38.1 R30.1 R33.2 U9.3 | length 201.8
  Top Layer w12: U9.3@525.36,3951.56 525.36,3908.76 R33.2@543.77,3890.35
  Top Layer w15: R33.2@543.77,3890.35 C38.1@608.7,3890.35 608.7,3958.29 R30.1@608.77,3958.35
NetC39_1: C39.1 R34.2 U10.3 U10.4 | length 116.8
  Top Layer w10: C39.1@1993.42,5931.1 2003.81,5941.49 2024.42,5941.49 2033.25,5932.65 2033.25,5919.33 ; U10.3@2045.11,5919.33 2033.25,5919.33 ; U10.4@2045.35,5893.49 2031.42,5893.49 2027.42,5897.49 2027.42,5913.49 2033.25,5919.33
NetC40_1: C40.1 R72.2 TP30.1 U10.1 | length 374.1
  Top Layer w10: U10.1@2087.48,5893.49 2101.05,5879.92
  Top Layer w20: TP30.1@2062.35,6054.49 2114.12,6054.49 2191,5977.62 2191,5892.35 R72.2@2198,5885.35 2196.51,5883.85 C40.1@2138.42,5883.85 2134.49,5879.92 2101.05,5879.92
NetC47_2: C47.2 C48.1 R61.1 U12.2
NetC49_2: C49.2 C50.1 L5.2 R40.1
NetC51_2: C51.2 L5.1 U12.3 | length 268.1
  Top Layer w20: U12.3@1945.28,5512.09 1987.01,5512.09 1995.42,5520.49 1995.42,5626.49 2054.5,5685.58 C51.2@2054.5,5710.49
NetC56_1: C56.1 R44.2 U14.3 U14.4 | length 116.8
  Top Layer w10: C56.1@1994.07,5037.41 2004.47,5047.8 2025.07,5047.8 2033.91,5038.97 2033.91,5025.64 ; U14.3@2045.76,5025.64 2033.91,5025.64 ; U14.4@2046.01,4999.8 2032.07,4999.8 2028.07,5003.8 2028.07,5019.8 2033.91,5025.64
NetC57_1: C57.1 R77.2 TP38.1 U14.1 | length 370.1
  Top Layer w10: U14.1@2088.13,4999.8 2101.7,4986.23
  Top Layer w20: TP38.1@2062.35,5146.85 2129,5146.85 2192.47,5083.38 2192.47,4998.84 2199.47,4991.84 R77.2@2197.98,4990.35 2197.8,4990.16 C57.1@2139.07,4990.16 2135.14,4986.23 2101.7,4986.23
NetC64_2: C64.2 C65.1 R63.1 U15.2
NetC66_2: C66.2 C67.1 L6.2 R47.1
NetC68_2: C68.2 L6.1 U15.3 | length 243.2
  Top Layer w20: U15.3@1945.94,4618.4 1987.67,4618.4 1996.07,4626.8 1996.07,4732.8 C68.2@2055.16,4791.89
NetC70_1: C70.1 C72.1 L7.2 R57.1 R58.2 R59.1 TP19.1 | length 720.8
  Top Layer w10: TP19.1@2076.77,3578.85 2044.15,3546.23 2044.15,3431.73 2063.03,3412.85 2219.77,3412.85 R59.1@2225.77,3418.85 ; R57.1@2243.82,3631.85 2244.82,3632.85 2419.59,3632.85 2460.01,3592.43 R58.2@2460.01,3530.03 2428.01,3530.03 C70.1@2399.34,3501.37
NetC70_2: C70.2 R58.1 R60.2 U18.2 | length 159.2
  Top Layer w10: U18.2@2358.92,3475.54 2399.19,3475.54 C70.2@2399.34,3475.39 2452.61,3475.39 R58.1@2460.01,3482.79 R60.2@2460.01,3427.85
NetC71_1: C71.1 R65.1 U18.1 U18.7 | length 207.2
  Top Layer w10: R65.1@2171.92,3446.46 2181.39,3446.46 2198.3,3463.38 C71.1@2248.34,3463.38 2273.29,3463.38 2285.45,3475.54 U18.7@2305.77,3475.54 2322.08,3475.54 2341.77,3455.85 U18.1@2358.92,3455.85
NetC73_1: C73.1 C103.1 J7.2 U19.1 U27.1
NetC74_1: C74.1 R93.2 R94.2 TP61.1 U19.9 | length 705.3
  Top Layer w15: R93.2@1456.62,928 1710,928 TP61.1@1762,876
  Bottom Layer w15: U19.9@1609,561 1762,714 TP61.1@1762,876
NetC76_1: C76.1 U19.7 U19.11 | length 429
  Top Layer w20: C76.1@1407.5,474 1409,475.5 U19.7@1409,561 1409,678 1509,778 U19.11@1509,861
NetC80_1: C80.1 U20.4 | length 88.6
  Top Layer w15: C80.1@2227.5,595 2227.5,651.82 2245.28,669.6 U20.4@2251.88,669.6
NetC81_1: C81.1 U21.5 | length 72.3
  Top Layer w8: 2369.28,5958.85 2378.91,5968.48 U21.5@2405.03,5968.48
  Top Layer w15: C81.1@2344.46,5940.06 2350.49,5940.06 2369.28,5958.85
NetC84_1: C84.1 U23.5 | length 72.3
  Top Layer w8: 2363.8,5078.72 2373.43,5088.35 U23.5@2399.56,5088.35
  Top Layer w15: C84.1@2338.99,5059.93 2345.02,5059.93 2363.8,5078.72
NetC87_2: C87.2 C88.2 C89.2 R82.1 R85.1 T3.2 U26.2 | length 520.6
  Top Layer w20: R85.1@703.24,1975.85 703.24,2075.65 723.44,2095.85 ; C88.2@703.24,2207.85 703.24,2116.05 723.44,2095.85 ; T3.2@987,2100.85 896.13,2100.85 C89.2@888.64,2108.35 876.14,2095.85 U26.2@754.88,2095.85 723.44,2095.85
NetC90_2: C90.2 C91.1 R84.2 R90.1 U25.1 | length 223.1
  Top Layer w10: 1923.86,2223.39 1934.01,2213.24 U25.1@1950.46,2213.24 1957,2219.78 1957,2241.25
  Top Layer w20: R90.1@1809.08,2238.67 1809.08,2286.93 1837.07,2314.93 R84.2@1837.07,2388.67
NetC92_1: C92.1 C93.1 R83.1 R86.2 U25.10 | length 117
  Top Layer w10: U25.10@2060.7,2213.24 2083.76,2213.24 2093.86,2223.34
  Top Layer w15: 2093.86,2223.34 2093.86,2280.34 2109.86,2296.34
NetC92_2: C92.2 R86.1 R88.2 U25.9 | length 125
  Top Layer w10: U25.9@2060.7,2193.55 2107.02,2193.55 2155.64,2242.17 R86.1@2165.58,2242.17
NetC94_1: C94.1 C95.1 D25.1 R84.1 TP55.1
NetC96_1: C96.1 C97.1 R87.2 R92.1 U25.6 | length 117
  Top Layer w10: U25.6@2060.7,2134.5 2083.76,2134.5 2093.86,2124.39
  Top Layer w15: 2093.86,2124.39 2093.86,2067.39 2109.86,2051.39
NetC96_2: C96.2 R87.1 R91.2 U25.7 | length 125.2
  Top Layer w10: U25.7@2060.7,2154.18 2116.56,2154.18 R87.1@2165.58,2105.17
NetC98_1: C98.1 U25.3 | length 78.5
  Top Layer w10: C98.1@1872.07,2173.67 1872.27,2173.87 U25.3@1950.46,2173.87
NetC99_2: C99.2 C100.2 D26.2 R89.1 TP59.1
NetC101_2: C101.2 C102.1 R89.2 U25.5 | length 85
  Top Layer w10: 1917.86,2103.39 1917.86,2118.34 1934.01,2134.5 U25.5@1950.46,2134.5 1957,2127.96 1957,2106.48
NetC104_1: C104.1 R95.2 U27.6
NetD1_2: D1.2 T1.6 | length 117
  Top Layer w30: T1.6@1393.38,3031.02 1417.89,3031.02 1444.81,3057.94 D1.2@1499.27,3057.94
NetD2_2: D2.2 T2.6 | length 117
  Top Layer w30: T2.6@1393.38,1580.93 1417.89,1580.93 1444.81,1607.85 D2.2@1499.27,1607.85
NetD3_2: D3.2 T1.4 | length 117
  Top Layer w30: T1.4@1393.38,2790.87 1417.89,2790.87 1444.81,2763.94 D3.2@1499.27,2763.94
NetD4_2: D4.2 T2.4 | length 117
  Top Layer w30: T2.4@1393.38,1340.77 1417.89,1340.77 1444.81,1313.85 D4.2@1499.27,1313.85
NetD7_2: D7.2 R7.1 | length 76.4
  Top Layer w20: D7.2@2174.22,1689.76 2175.22,1690.76 R7.1@2250.25,1690.76
NetD8_2: D8.2 R6.1 | length 76.4
  Top Layer w20: D8.2@2174.22,3139.86 2175.22,3140.86 R6.1@2250.25,3140.86
NetD11_2: D11.2 R11.1 | length 233.8
  Top Layer w20: D11.2@1676.25,4375.85 1696.25,4395.85 1876.27,4395.85 R11.1@1894.27,4377.85
NetD13_2: D13.2 R24.1 | length 71.3
  Top Layer w20: R24.1@2482.26,3895.96 2482.26,3826.75 D13.2@2483.77,3825.24
NetD17_2: D17.2 R41.1 | length 66.5
  Top Layer w15: D17.2@2357.38,5813.54 R41.1@2423.85,5813.54
NetD21_2: D21.2 R48.1 | length 66.5
  Top Layer w15: D21.2@2358.04,4919.85 R48.1@2424.5,4919.85
NetD22_1: D22.1 Q1.1 Q1.2 Q1.5 Q1.6 Q1.8 | length 240.8
  Top Layer w12: Q1.6@644.23,5238.62 609.09,5238.62 600,5247.72 600,5351.8 618.63,5370.43 D22.1@681,5370.43
NetD22_2: D22.2 R54.1 | length 91.2
  Top Layer w20: R54.1@604.5,5407.6 640.07,5443.17 D22.2@681,5443.17
NetD23_2: D23.2 R75.2 | length 70.8
  Top Layer w15: D23.2@2231.11,6208.48 2232.11,6207.48 R75.2@2301.5,6207.48
NetD24_2: D24.2 R80.2 | length 70.8
  Top Layer w15: D24.2@2225.64,5328.35 2226.64,5327.35 R80.2@2296.03,5327.35
NetD25_2: D25.2 D26.1 T3.6
NetJ3_2: J3.2 R15.2 U5.6 | length 433.5
  Top Layer w15: U5.6@2163.06,4196.44 2189.36,4196.44 2198.77,4205.85 v1(2201.77,4202.85) ; R15.2@2309.39,4112.85 2388.77,4112.85 J3.2@2431.77,4155.85
  Bottom Layer w15: v1(2201.77,4202.85) 2248.77,4155.85 J3.2@2431.77,4155.85
NetJ4_2: J4.2 R32.1
  other v1: 71.77,3739.27 109.77,3739.27 71.77,3777.27 109.77,3777.27
NetL3_2: L3.2 U5.5 | length 114.7
  Top Layer w15: U5.5@2163.06,4170.85 L3.2@2277.71,4170.85 ; L3.2@2289.77,4170.91 L3.2@2289.77,4170.91
NetL4_2: L4.2 R23.1 | length 78.7
  Top Layer w20: L4.2@1995.77,3887.29 2015.71,3887.29 R23.1@2057.27,3928.85
NetL7_1: L7.1 U18.6 | length 127
  Top Layer w12: 2211.77,3495.22 U18.6@2305.77,3495.22
  Top Layer w20: L7.1@2179.34,3493.85 2180.71,3495.22 2211.77,3495.22
NetL8_1: L8.1 R94.1 R95.1
NetQ1_3: Q1.3 R55.1 | length 63.6
  Top Layer w12: Q1.3@721,5289.8 765.5,5289.8 R55.1@779,5303.3
NetR3_2: R3.2 U1.5 | length 208.1
  Top Layer w15: R3.2@640.25,1340.85 605.74,1340.85 591.74,1354.85 591.74,1448.85 603.74,1460.85 U1.5@646.61,1460.85
NetR13_1: R13.1 R17.2 U5.2 | length 100.5
  Top Layer w15: R13.1@1974.11,4171.23 1974.5,4170.85 U5.2@2074.48,4170.85
NetR14_1: R14.1 TP13.1 U6.3 | length 167.9
  Top Layer w10: R14.1@817.26,4066.85 TP13.1@888.77,4066.85 983.76,4066.85 U6.3@984.76,4065.85
NetR16_1: R16.1 TP15.1 U6.4 | length 172.9
  Top Layer w10: R16.1@817.26,4002.85 830.26,4015.85 TP15.1@888.77,4015.85 U6.4@984.76,4015.85
NetR18_1: R18.1 TP18.1 U6.5 | length 179.1
  Top Layer w10: R18.1@817.26,3937.85 845.26,3965.85 TP18.1@888.77,3965.85 U6.5@984.76,3965.85
NetR19_1: R19.1 TP21.1 U6.6 | length 185.7
  Top Layer w10: R19.1@817.26,3871.85 861.26,3915.85 TP21.1@888.77,3915.85 U6.6@984.76,3915.85
NetR20_1: R20.1 U6.7 | length 191.9
  Top Layer w10: R20.1@817.26,3806.85 854.77,3806.85 913.77,3865.85 U6.7@984.76,3865.85
NetR21_2: R21.2 R22.2 U6.10 | length 178.6
  Top Layer w15: U6.10@1358.77,3865.85 1458.77,3865.85 R21.2@1469.77,3854.85 R22.2@1469.77,3791.85
NetR25_2: R25.2 U8.1 | length 72.7
  Top Layer w15: U8.1@616.06,3608.4 652.77,3608.4
  Top Layer w20: 653.32,3607.85 R25.2@689.27,3607.85
NetR26_1: R26.1 R28.2 R29.2 TP31.1 | length 524.4
  Top Layer w15: R28.2@566.83,3734.85 567.77,3735.79 v1(567.77,3697.85) ; R26.1@605.26,3544.85 v1(647.77,3544.85) R29.2@689.27,3544.85 689.27,3508.41 703.92,3493.76 TP31.1@861.77,3493.76
  Bottom Layer w15: v1(567.77,3697.85) 567.77,3624.85 v1(647.77,3544.85)
NetR31_1: R31.1 U9.1 | length 65.3
  Top Layer w15: R31.1@473.77,3886.41 473.77,3951.15 U9.1@474.18,3951.56
NetR55_2: R55.2 U17.4 | length 61.9
  Top Layer w10: R55.2@779,5240.31 780.2,5241.51 U17.4@840.41,5241.51
NetR56_2: R56.2 U17.2 | length 71.2
  Top Layer w10: U17.2@866,5330.09 R56.2@866,5401.31
NetR59_2: R59.2 TP54.1 U18.8 | length 595
  Top Layer w12: R59.2@2251.76,3418.85 v1(2290.74,3418.85) 2305.77,3433.87 U18.8@2305.77,3455.66
  Bottom Layer w12: TP54.1@1888.22,3578.85 1888.22,3503.39 1972.77,3418.85 v1(2290.74,3418.85)
NetR71_1: R71.1 TP17.1 U8.3 | length 363.2
  Top Layer w12: U8.3@616.06,3659.58 624.7,3659.58 641.77,3676.65 v1(641.77,3686.85) 641.77,3708.85 TP17.1@629.77,3720.85
  Top Layer w15: R71.1@604.26,3479.14 v1(646.77,3479.14)
  Bottom Layer w12: v1(641.77,3686.85) 681.77,3646.85 681.77,3514.14 v1(646.77,3479.14)
NetR73_1: R73.1 R76.2 U21.3 | length 110.5
  Top Layer w8: U21.3@2428.65,5988.16 2428.65,6016.85
  Top Layer w15: R73.1@2428.22,6098.48 2428.65,6098.05 2428.65,6016.85
NetR74_2: R74.2 U21.4 U22.2 | length 117.1
  Top Layer w8: 2385.31,5988.16 U21.4@2405.03,5988.16
  Top Layer w15: U22.2@2344.46,6045.19 R74.2@2344.46,5989.06 2345.36,5988.16 2385.31,5988.16
NetR75_1: R75.1 U22.4 | length 76
  Top Layer w15: R75.1@2364.5,6207.48 2370.05,6201.92 U22.4@2370.05,6133.77
NetR78_1: R78.1 R81.2 U23.3 | length 110.5
  Top Layer w8: U23.3@2423.18,5108.03 2423.18,5136.72
  Top Layer w15: R78.1@2422.75,5218.35 2423.18,5217.91 2423.18,5136.72
NetR79_2: R79.2 U23.4 U24.2 | length 117.1
  Top Layer w8: 2379.84,5108.03 U23.4@2399.56,5108.03
  Top Layer w15: U24.2@2338.99,5165.06 R79.2@2338.99,5108.93 2339.89,5108.03 2379.84,5108.03
NetR80_1: R80.1 U24.4 | length 76
  Top Layer w15: R80.1@2359.02,5327.35 2364.58,5321.79 U24.4@2364.58,5253.64
NetR85_2: R85.2 U26.5 | length 208.1
  Top Layer w15: R85.2@640.25,1975.85 605.74,1975.85 591.74,1989.85 591.74,2083.85 603.74,2095.85 U26.5@646.61,2095.85
NetR90_2: R90.2 U25.2 | length 97.1
  Top Layer w10: R90.2@1872.07,2238.67 1917.19,2193.55 U25.2@1950.46,2193.55
NetR91_1: R91.1 U25.8 | length 236.4
  Top Layer w10: U25.8@2060.7,2173.87 2143.39,2173.87 2143.86,2173.39
  Top Layer w15: 2143.86,2173.39 2292.35,2173.39 R91.1@2295.58,2170.17
NetR93_1: R93.1 U19.12 | length 67.2
  Top Layer w15: U19.12@1409,861 1409,927.62 R93.1@1409.38,928
NetT1_1: T1.1 U2.1 | length 349
  Top Layer w25: U2.1@633.09,2949.44 649.22,2949.44 732.42,3032.65 T1.1@947.63,3032.65
NetT1_3: T1.3 U2.3 | length 349.7
  Top Layer w25: U2.3@633.09,2874.64 643.86,2874.64 727.64,2790.87 T1.3@948.11,2790.87
NetT2_1: T2.1 U1.3 | length 227.5
  Top Layer w25: U1.3@754.88,1498.25 769.14,1498.25 851.82,1580.93 T2.1@948.11,1580.93
NetT2_3: T2.3 U1.1 | length 227.5
  Top Layer w25: U1.1@754.88,1423.45 769.14,1423.45 851.82,1340.77 T2.3@948.11,1340.77
NetT3_1: T3.1 U26.3 | length 260.1
  Top Layer w25: U26.3@754.88,2133.25 769.14,2133.25 836.74,2200.85 T3.1@987,2200.85
NetT3_3: T3.3 U26.1 | length 256
  Top Layer w25: U26.1@754.88,2058.45 769.14,2058.45 826.74,2000.85 T3.3@987,2000.85
NetTP9_1: TP9.1 U3.3 | length 106.1
  Top Layer w15: TP9.1@1891.74,1306.76 1948.89,1363.91 U3.3@1948.89,1389.16
NetTP10_1: TP10.1 U4.3 | length 106.1
  Top Layer w15: TP10.1@1891.74,2756.86 1948.89,2814 U4.3@1948.89,2839.26
NetU9_4: U9.4 U9.5 | length 92
  Top Layer w12: U9.5@499.77,4040.14 499.77,4071.85 503.77,4075.85 520.77,4075.85 525.36,4071.26 U9.4@525.36,4040.14
SCLK: R14.2 TP45.1 | length 81.5
  Top Layer w10: TP45.1@672.77,4066.85 R14.2@754.27,4066.85
SDI: R16.2 TP46.1 | length 81.5
  Top Layer w10: TP46.1@672.77,4002.85 R16.2@754.27,4002.85
SDO: R19.2 TP48.1 | length 81.5
  Top Layer w10: TP48.1@672.77,3871.85 R19.2@754.27,3871.85
VCC_LS_3: C36.2 R10.2 R25.1 R27.1 TP29.1 | length 91
  Top Layer w20: v1(729.26,4393.35) R10.2@729.26,4349.85 v1(776.77,4349.85)
  other v1: 803.77,3734.85 845.77,3734.85 887.77,3734.85
VCC_LS_4: C69.1 R35.2 R54.2 R56.1 TP36.1 U13.8 U17.5 | length 788.3
  Top Layer w15: U13.8@463.13,5406.98 540.89,5406.98 R54.2@541.5,5407.6
  Top Layer w20: v1(750.48,5401.8) R56.1@803.5,5401.8 ; U17.5@891.59,5241.51 950.2,5241.51 C69.1@951,5242.31 v1(951,5197.8)
  Bottom Layer w20: v1(505,5454.8) 694,5454.8 v1(951,5197.8)
VCC_LS_5: R37.2 TP39.1 U13.5 | length 42.3
  Top Layer w15: U13.5@463.13,5330.21 464.49,5331.57 488.05,5331.57 490.26,5333.79 504,5333.79
pads on no net: FID1.1 FID2.1 FID3.1 FID4.1 FID5.1 FID6.1 Q1.0 T3.5 U3.4 U4.4 U7.4 U12.4 U12.5 U15.4 U15.5 U17.1 U18.4 U19.2 U19.10 U19.18 U22.1 U24.1 U25.11@1995.74,2113.63 U25.11@1995.74,2234.1 U25.11@2005.58,2149.06 U25.11@2005.58,2198.67 U25.11@2015.42,2113.63 U25.11@2015.42,2234.1 U27.7 U27.8 U27.14

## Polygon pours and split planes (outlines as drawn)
NetC73_1 on Top Layer "vdd" (solid, remove dead copper, pour order 365): 22 vertices, not listed, extent 105,33 952.55,593
GND_6 on Top Layer "vdd" (solid, remove dead copper, pour order 266): 602,619 453.02,619 355.02,521 112,521 105,528 105,915 135.4,942.6 136.81,944 927,944 943,928 943,825 737,619
NetC104_1 on Top Layer "vdd" (solid, remove dead copper, pour order 363): 1493.53,231.2 1377,114.67 1377,54 1389,42 1430,42 1441,53 1441,103.54 1513.46,176 1775.77,176 1781.77,182 1781.77,227.18 1777.74,231.2
NetL8_1 on Top Layer "vdd" (solid, remove dead copper, pour order 361): 1818,158 1928.79,158 1943.93,173.14 1943.93,586.27 1937.2,593 1809.48,593 1805.48,589 1805.48,170.52
NetC74_1 on Top Layer "vdd" (solid, remove dead copper, pour order 359): 1784,455 1775,446 1596,446 1578,464 1578,582.55 1587.04,591.59 1778.41,591.59 1784,586
GND_BI on Top Layer "vdd" (solid, remove dead copper, pour order 358): 1555,2261.85 1546,2252.85 1546,2101.85 1552,2095.85 1750,2095.85 1757,2102.85 1757,2251.98 1747.13,2261.85
NetC94_1 on Top Layer "vdd" (solid, remove dead copper, pour order 356): 1795,2483.1 1784.25,2493.85 1499,2493.85 1414,2408.85 1414,2316.85 1423,2307.85 1660,2307.85 1683,2284.85 1766.02,2284.85 1795,2313.83
NetC99_2 on Top Layer "vdd" (solid, remove dead copper, pour order 354): 1782.46,2057.85 1796,2044.31 1796,1882.85 1779,1865.85 1443,1865.85 1431.55,1877.3 1431.55,2012.65 1442.75,2023.85 1509,2023.85 1543,2057.85
NetD25_2 on Top Layer "vdd" (solid, remove dead copper, pour order 352): 1491,2234.85 1499,2226.85 1499,2080.85 1490,2071.85 1422,2071.85 1413,2080.85 1413,2141.85 1402,2152.85 1331,2152.85 1325,2158.85 1325,2225.85 1334,2234.85
+5.0V_3.3V_VDC_5 on Top Layer "vdd" (solid, remove dead copper, pour order 344): 25 vertices, not listed, extent 2170.11,4781.8 2518.58,5074.85
NetC90_2 on Top Layer "dg" (solid, remove dead copper, pour order 340): 1961.86,2217.39 1961.86,2440.39 1952.86,2449.39 1822.86,2449.39 1816.86,2443.39 1816.86,2362.39 1912.86,2266.39 1912.86,2229.39 1912.86,2212.39 1916.86,2208.39 1919.86,2205.39 1954.86,2205.39 1959.86,2205.39 1961.86,2207.39
NetC101_2 on Top Layer "dg" (solid, remove dead copper, pour order 338): 1961.86,2130.34 1961.86,1907.34 1952.86,1898.34 1822.86,1898.34 1816.86,1904.34 1816.86,1985.34 1912.86,2081.34 1912.86,2118.34 1912.86,2135.34 1916.86,2139.34 1919.86,2142.34 1954.86,2142.34 1959.86,2142.34 1961.86,2140.34
NetC96_1 on Top Layer "dg" (solid, remove dead copper, pour order 336): 2326.86,1983.39 2326.86,1929.39 2319.86,1922.39 2209.86,1922.39 2202.86,1929.39 2202.86,2003.91 2194.12,2012.65 2103.71,2012.65 2093.61,2022.76 2093.61,2056.13 2100.65,2063.18 2317.82,2063.43 2326.86,2054.39
NetC96_2 on Top Layer "dg" (solid, remove dead copper, pour order 334): 2245.86,2084.39 2130.86,2084.39 2126.86,2088.39 2126.86,2135.39 2137.86,2146.39 2247.42,2146.39 2259.12,2134.69 2317.82,2134.69 2324.12,2128.39 2324.12,2093.66 2314.86,2084.39
NetC92_1 on Top Layer "dg" (solid, remove dead copper, pour order 332): 18 vertices, not listed, extent 2093.61,2283.98 2326.86,2424.95
NetC92_2 on Top Layer "dg" (solid, remove dead copper, pour order 330): 2245.86,2262.95 2133.41,2262.95 2126.86,2256.39 2126.86,2222.82 2137.04,2212.65 2259.12,2212.65 2317.82,2212.65 2324.12,2218.95 2324.12,2259.13 2320.31,2262.95
GND_BI on Top Layer "dg" (solid, remove dead copper, pour order 328): 25 vertices, not listed, extent 1981.86,1896.39 2180.86,2452.39
NetC87_2 on Top Layer "vdd" (solid, remove dead copper, pour order 322): 17 vertices, not listed, extent 378.2,2180.65 739.74,2346.85
+5V_B on Top Layer "vdd" (solid, remove dead copper, pour order 320): 262.2,2198.39 224.74,2235.85 118.74,2235.85 110.74,2227.85 110.74,2135.85 122.74,2123.85 433.74,2123.85 438.74,2128.85 438.74,2192.45 432.8,2198.39
GND_B on Top Layer "vdd" (solid, remove dead copper, pour order 318): 23 vertices, not listed, extent 110.74,1895.85 669.27,2231.87
GND_VDC_6 on Top Layer "vdd" (solid, remove dead copper, pour order 278): 21 vertices, not listed, extent 1981,483 2407,708.61
+3.3V_6 on Top Layer "vdd" (solid, remove dead copper, pour order 276): 2227.74,917.33 2237.42,927 2385,927 2395,917 2395,736 2384,725 2232.74,725 2227.74,730
+5V_VDC_6 on Top Layer "vdd" (solid, remove dead copper, pour order 272): 21 vertices, not listed, extent 1806,624 2186.74,933
GND_VDC_6 on Top Layer "vdd" (solid, remove dead copper, pour order 270): 17 vertices, not listed, extent 1477,531 1823,796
